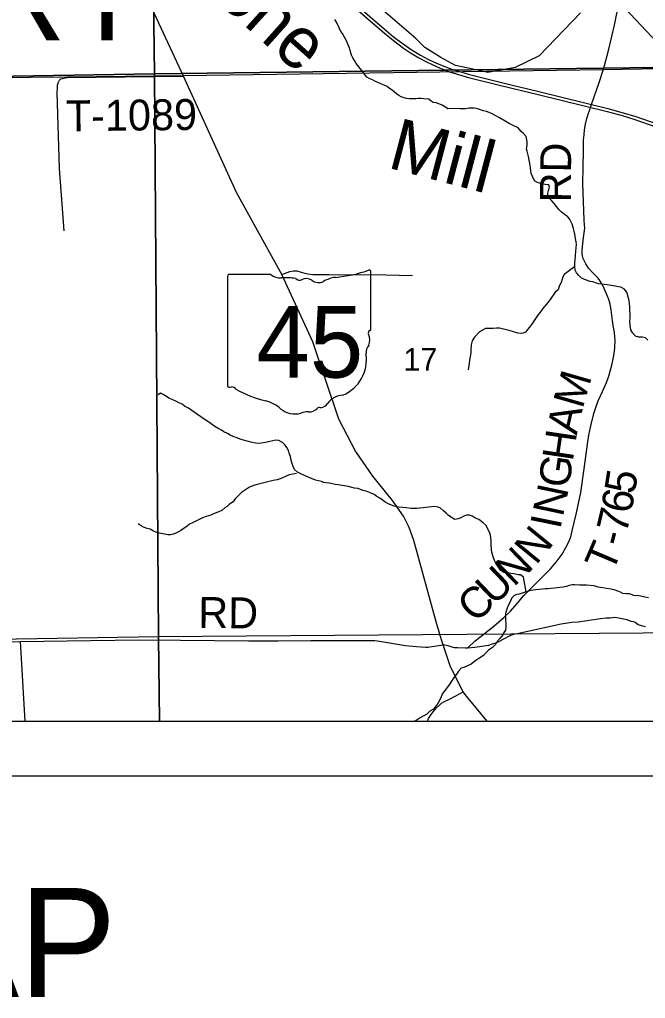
# Model space of a CAD drawing. Extents: x 0 to 34, y 0 to 22.
# Drawn here: x 6.27 to 7.419, y 13.591 to 15.389 of the extents above; entities that cross this region are included whole.
import ezdxf

# ---------------------------------------------------------------- set-up
doc = ezdxf.new("R2010")
doc.units = 0
for name, color, linetype in [('Default', 7, 'Continuous'), ('GM_X_County_Road', 7, 'Continuous'), ('GM_X_County_Road_Text', 7, 'Continuous'), ('GM_X_Minor_River', 7, 'Continuous'), ('GM_X_Minor_River_Text', 7, 'Continuous'), ('GM_X_Rail_Line', 7, 'Continuous'), ('GM_X_Section', 7, 'Continuous'), ('GM_X_Section_Text', 7, 'Continuous'), ('GM_X_State_Location', 7, 'Continuous'), ('GM_X_State_Route', 7, 'Continuous'), ('GM_X_State_Shield', 7, 'Continuous'), ('GM_X_Township', 7, 'Continuous'), ('GM_X_Township_Road', 7, 'Continuous'), ('GM_X_Township_Road_Text', 7, 'Continuous'), ('GM_X_Township_Text', 7, 'Continuous'), ('SH_Cut_Line', 7, 'Continuous'), ('SH_Data', 7, 'Continuous'), ('SH_Text', 7, 'Continuous')]:
    doc.layers.add(name, color=color, linetype=linetype)

msp = doc.modelspace()

# ---------------------------------------------------------------- linework, layer by layer
at = {"layer": 'Default'}
for points in [[(6.527, 14.1), (7.4967, 14.1), (7.496, 14.2624), (6.5252, 14.2552)], [(5.5573, 14.1), (6.527, 14.1), (6.5252, 14.2552), (5.5565, 14.239), (5.5568, 14.2045)]]:
    msp.add_lwpolyline(points, close=True, dxfattribs=at)
at = {"layer": 'GM_X_County_Road'}
msp.add_lwpolyline([(6.1042, 14.2452), (6.2723, 14.2468), (6.4008, 14.2484), (6.4904, 14.2496), (6.5656, 14.249), (6.6904, 14.2481), (6.7452, 14.2479), (6.8053, 14.2482), (6.9126, 14.2485), (6.9224, 14.2483), (6.9269, 14.2479), (6.9311, 14.2473), (6.9603, 14.2421), (6.9789, 14.2394), (6.999, 14.2375), (7.0164, 14.2363), (7.0179, 14.2362), (7.0197, 14.2363), (7.0227, 14.2367), (7.0279, 14.2375), (7.0479, 14.2406)], dxfattribs=at)
at = {"layer": 'GM_X_Minor_River'}
for points in [[(7.2413, 15.0755), (7.243, 15.0812), (7.2422, 15.0857), (7.2353, 15.0864), (7.23, 15.0866), (7.2251, 15.0888), (7.2201, 15.0906), (7.2159, 15.0928), (7.2095, 15.1067), (7.2077, 15.1211), (7.2047, 15.1378), (7.2023, 15.1476), (7.201, 15.1518), (7.202, 15.1583), (7.2023, 15.1643), (7.2018, 15.1685), (7.2006, 15.1746), (7.1955, 15.1802), (7.1913, 15.1839), (7.1855, 15.1902), (7.1767, 15.1946), (7.169, 15.1986), (7.1629, 15.2023), (7.1517, 15.2085), (7.138, 15.2158), (7.1322, 15.2183), (7.1273, 15.2201), (7.1223, 15.2215), (7.1093, 15.2258), (7.1052, 15.2265), (7.0953, 15.2263), (7.0893, 15.2254), (7.0836, 15.2252), (7.079, 15.2255), (7.0684, 15.2257), (7.0563, 15.2254), (7.0521, 15.2284), (7.046, 15.232), (7.0402, 15.2342), (7.0349, 15.236), (7.0299, 15.237), (7.0257, 15.2396), (7.0215, 15.2429), (7.0128, 15.2439), (7.0078, 15.2445), (7.0021, 15.2444), (6.998, 15.2439), (6.9923, 15.2434), (6.9862, 15.2437), (6.9809, 15.2443), (6.9767, 15.2453), (6.971, 15.2471), (6.9668, 15.2497), (6.9622, 15.2526), (6.9541, 15.2593), (6.9495, 15.2626), (6.9452, 15.2663), (6.9399, 15.2689), (6.9334, 15.2714), (6.9223, 15.2761), (6.9181, 15.2783), (6.912, 15.2808), (6.9078, 15.2834), (6.9039, 15.289), (6.8988, 15.2954), (6.893, 15.3025), (6.8883, 15.3088), (6.8852, 15.3141), (6.8824, 15.319), (6.8797, 15.3238), (6.8772, 15.3322), (6.8752, 15.3386), (6.87, 15.3514), (6.8672, 15.3567), (6.8633, 15.3634), (6.8602, 15.3675), (6.8574, 15.3743), (6.8523, 15.3848), (6.8491, 15.3897)], [(7.4235, 14.8004), (7.4192, 14.8048), (7.4132, 14.8058), (7.4071, 14.8057), (7.4014, 14.8078), (7.3963, 14.8134), (7.3928, 14.8194), (7.3911, 14.8278), (7.391, 14.8346), (7.3912, 14.8418), (7.3908, 14.862), (7.3899, 14.8669), (7.3894, 14.8734), (7.3878, 14.879), (7.3865, 14.8851), (7.3838, 14.8896), (7.381, 14.8937), (7.3741, 14.8974), (7.3699, 14.898), (7.3639, 14.8994), (7.3494, 14.9018), (7.3384, 14.9031), (7.3338, 14.9037), (7.3293, 14.9051), (7.3228, 14.9073), (7.3175, 14.9083), (7.3129, 14.9101), (7.3072, 14.9119), (7.3014, 14.9148), (7.2972, 14.9189), (7.2925, 14.9237), (7.2901, 14.929), (7.2896, 14.9354), (7.2899, 14.9423), (7.2901, 14.9476), (7.2911, 14.9552), (7.2917, 14.9636), (7.2923, 14.9697), (7.2926, 14.9758), (7.2921, 14.9811), (7.2912, 14.9872), (7.2895, 14.9948), (7.2883, 15.0004), (7.2874, 15.0057), (7.285, 15.0133), (7.2802, 15.0231), (7.276, 15.0275), (7.271, 15.0312), (7.2652, 15.0353), (7.2606, 15.0401), (7.252, 15.0514), (7.2477, 15.0562), (7.2427, 15.061), (7.2403, 15.0659), (7.2402, 15.0705), (7.2413, 15.0755)], [(7.2896, 14.9354), (7.2702, 14.9209), (7.2677, 14.9167), (7.2662, 14.9125), (7.2649, 14.906), (7.2612, 14.8994), (7.2591, 14.8929), (7.2539, 14.8883), (7.2443, 14.8747), (7.2406, 14.8701), (7.2343, 14.862), (7.2306, 14.8577), (7.2266, 14.8523), (7.2233, 14.848), (7.2192, 14.8426), (7.2163, 14.838), (7.2119, 14.8314), (7.2063, 14.8241), (7.203, 14.8198), (7.1989, 14.8152), (7.1948, 14.8132), (7.1899, 14.8127), (7.1853, 14.8134), (7.1693, 14.8183), (7.164, 14.8194), (7.1564, 14.8211), (7.1514, 14.8221), (7.1461, 14.8224), (7.1397, 14.8219), (7.1257, 14.8216), (7.1205, 14.8188), (7.1148, 14.8156), (7.1056, 14.8059), (7.1012, 14.799), (7.0994, 14.7917), (7.0989, 14.7826), (7.0986, 14.7769), (7.0966, 14.7635), (7.0956, 14.7574), (7.0939, 14.7456)], [(6.6291, 14.6419), (6.6176, 14.6496), (6.6095, 14.6552), (6.603, 14.6592), (6.5868, 14.671), (6.5803, 14.6751), (6.5734, 14.6791), (6.5691, 14.6824), (6.5626, 14.6853), (6.5584, 14.6875), (6.5504, 14.6915), (6.5443, 14.694), (6.5401, 14.697), (6.5343, 14.7003), (6.529, 14.7028), (6.5248, 14.7001)], [(7.2001, 14.3382), (7.1954, 14.3649), (7.19, 14.3689), (7.1859, 14.3692), (7.1809, 14.3703), (7.1653, 14.3726), (7.1596, 14.3736), (7.1535, 14.378), (7.1484, 14.3848), (7.1453, 14.3893), (7.1421, 14.3957), (7.1401, 14.4021), (7.1376, 14.4108), (7.1368, 14.4149), (7.1362, 14.4244), (7.1361, 14.4305), (7.1356, 14.4385), (7.1343, 14.4445), (7.1268, 14.4596), (7.1214, 14.4648), (7.1133, 14.4707), (7.1072, 14.4732), (7.1014, 14.4769), (7.0961, 14.4787), (7.0915, 14.479), (7.087, 14.4777), (7.0807, 14.4738), (7.0758, 14.4718), (7.0697, 14.4705), (7.0632, 14.4742), (7.0571, 14.4786), (7.0536, 14.4827), (7.0489, 14.4868), (7.0432, 14.4916), (7.0386, 14.4934), (7.0321, 14.4944), (7.0162, 14.4929), (7.0113, 14.492), (7.0045, 14.4915), (6.9996, 14.491), (6.9939, 14.4913), (6.9894, 14.4912), (6.9803, 14.4925), (6.9738, 14.4927), (6.9666, 14.4933), (6.9579, 14.4954), (6.9472, 14.4998), (6.943, 14.502), (6.9318, 14.5097), (6.9264, 14.513), (6.9214, 14.5167), (6.9157, 14.5192), (6.9065, 14.5228), (6.9008, 14.5242), (6.8917, 14.5275), (6.8852, 14.5285), (6.8738, 14.5316), (6.8662, 14.5326), (6.8552, 14.5346), (6.8498, 14.5353), (6.8396, 14.5373), (6.8335, 14.538), (6.8286, 14.5386), (6.8244, 14.5404), (6.8137, 14.5429), (6.8091, 14.5447), (6.8042, 14.5465), (6.7866, 14.5548), (6.7808, 14.5577), (6.7754, 14.5629), (6.7726, 14.5682), (6.7702, 14.5758), (6.769, 14.5799), (6.7677, 14.5867), (6.7653, 14.5928), (6.7641, 14.5973), (6.7609, 14.6029), (6.7582, 14.6074), (6.7528, 14.6123), (6.7463, 14.6159), (6.741, 14.6166), (6.7297, 14.614), (6.7221, 14.6124), (6.7142, 14.611), (6.7085, 14.6105), (6.7043, 14.6108), (6.7002, 14.6115), (6.6952, 14.6129), (6.6906, 14.6143), (6.6815, 14.6164), (6.6773, 14.6178), (6.6723, 14.6193), (6.6681, 14.6215), (6.6639, 14.6225), (6.6571, 14.6258), (6.6521, 14.6287), (6.6456, 14.632), (6.641, 14.6349), (6.636, 14.6375), (6.6291, 14.6419)], [(6.7786, 14.555), (6.7722, 14.5541), (6.7654, 14.5528), (6.7586, 14.55), (6.753, 14.5472), (6.7485, 14.5452), (6.7432, 14.5436), (6.7361, 14.5423), (6.7165, 14.5373), (6.7112, 14.5364), (6.7063, 14.5348), (6.6999, 14.5335), (6.6924, 14.53), (6.6853, 14.5252), (6.6778, 14.5201), (6.6663, 14.5089), (6.6623, 14.5031), (6.6559, 14.4991), (6.6518, 14.4945), (6.6473, 14.4921), (6.6414, 14.4874), (6.6361, 14.4846), (6.6279, 14.4818), (6.6215, 14.479), (6.6132, 14.4765), (6.6061, 14.4737), (6.6004, 14.4709), (6.5952, 14.4681), (6.5881, 14.4649), (6.5824, 14.4622), (6.578, 14.4586), (6.5664, 14.4508), (6.5619, 14.4484), (6.557, 14.4456), (6.5525, 14.4436), (6.5472, 14.4428), (6.5427, 14.4427), (6.5275, 14.4454), (6.5225, 14.4468), (6.516, 14.4493), (6.5099, 14.453), (6.5046, 14.4544), (6.4977, 14.4569), (6.4935, 14.4591), (6.4881, 14.4628)], [(7.425, 14.3266), (7.4182, 14.3283), (7.4132, 14.3294), (7.4071, 14.3304), (7.398, 14.3313), (7.39, 14.3342), (7.3847, 14.3344), (7.3779, 14.3351), (7.3733, 14.3372), (7.3637, 14.3408), (7.3561, 14.3426), (7.3477, 14.3443), (7.3409, 14.3453), (7.3325, 14.3466), (7.3253, 14.3487), (7.3109, 14.3503), (7.2984, 14.3504), (7.2893, 14.3506), (7.2847, 14.3505), (7.2791, 14.3496), (7.2742, 14.348), (7.2685, 14.3467), (7.2621, 14.3458), (7.2527, 14.3448), (7.2459, 14.3439), (7.2409, 14.3434), (7.2353, 14.3433), (7.2303, 14.3428), (7.2179, 14.3418), (7.213, 14.3409), (7.2088, 14.3405), (7.2001, 14.338), (7.1874, 14.3339), (7.1832, 14.3331), (7.1783, 14.3314), (7.1739, 14.3268), (7.1717, 14.321), (7.1684, 14.3152), (7.1655, 14.308), (7.1627, 14.2984), (7.1624, 14.2934), (7.1629, 14.2722), (7.1626, 14.2676), (7.1593, 14.2629), (7.1575, 14.2587), (7.1523, 14.2521), (7.1467, 14.2463), (7.1438, 14.2413), (7.1383, 14.2355), (7.1315, 14.2308), (7.1267, 14.2265), (7.1223, 14.2207), (7.1155, 14.2167), (7.1062, 14.2108), (7.0995, 14.205), (7.0927, 14.2022), (7.086, 14.1986), (7.0811, 14.1977), (7.0763, 14.1919), (7.0726, 14.1865), (7.0663, 14.1784), (7.0634, 14.1738), (7.059, 14.1672), (7.0513, 14.1564), (7.0468, 14.151), (7.0443, 14.1448), (7.0392, 14.1348), (7.03, 14.1221), (7.0237, 14.1185), (7.0181, 14.1131), (7.0061, 14.1063), (6.9964, 14.1004), (6.9957, 14.1)]]:
    msp.add_lwpolyline(points, dxfattribs=at)
at = {"layer": 'GM_X_Rail_Line'}
msp.add_lwpolyline([(5.5619, 14.1), (8.9, 14.1), (8.9, 17.3138), (8.2882, 17.3064), (7.4754, 17.3006), (7.4757, 17.0495), (7.4723, 16.4951), (7.4818, 15.827), (7.482, 15.8179), (7.4834, 15.2992), (7.3416, 15.297), (6.5709, 15.2859), (6.3575, 15.2833), (5.5569, 15.2761), (5.5579, 15.2049), (5.5588, 15.1747), (5.5581, 14.9676), (5.5583, 14.9347), (5.5595, 14.6439), (5.5615, 14.2414), (5.5608, 14.205)], close=True, dxfattribs=at)
for points in [[(7.2999, 15.4014), (7.2245, 15.3226), (7.1802, 15.3011), (7.1302, 15.2918), (7.1142, 15.2958), (7.0708, 15.3051), (7.044, 15.3194), (7.0144, 15.338), (6.9981, 15.3543), (6.9592, 15.3878), (6.6469, 15.6574)], [(6.875, 15.4204), (6.936, 15.3678), (6.9535, 15.3534), (6.9645, 15.3449), (6.9755, 15.337), (6.9882, 15.3283), (7.0036, 15.3191), (7.0174, 15.3117), (7.028, 15.3067), (7.041, 15.3008), (7.0599, 15.2935), (7.0948, 15.283), (7.1537, 15.2682), (7.2222, 15.2514), (7.349, 15.2202), (7.3768, 15.2128), (7.3998, 15.2059), (7.4385, 15.1923)], [(6.8787, 15.4247), (6.9396, 15.3721), (6.957, 15.3578), (6.9679, 15.3494), (6.9788, 15.3416), (6.9913, 15.333), (7.0064, 15.324), (7.0199, 15.3167), (7.0304, 15.3118), (7.0432, 15.306), (7.0618, 15.2988), (7.0963, 15.2885), (7.1551, 15.2736), (7.2235, 15.2569), (7.3504, 15.2257), (7.3784, 15.2182), (7.4016, 15.2113), (7.4405, 15.1976)]]:
    msp.add_lwpolyline(points, dxfattribs=at)
at = {"layer": 'GM_X_Section'}
for points in [[(6.5053, 16.2508), (7.4857, 16.2946), (7.4868, 15.3017), (6.5184, 15.2893)], [(5.5468, 16.2132), (6.5053, 16.2508), (6.5184, 15.2893), (5.5538, 15.2739)], [(5.5538, 15.2739), (6.5184, 15.2893), (6.5252, 14.2552), (5.5565, 14.239), (5.5548, 15.2004)], [(6.5184, 15.2893), (7.4868, 15.3017), (7.496, 14.2624), (6.5252, 14.2552)]]:
    msp.add_lwpolyline(points, close=True, dxfattribs=at)
at = {"layer": 'GM_X_State_Route'}
msp.add_line((7.1285, 14.1), (7.0908, 14.1463), dxfattribs=at)
for points in [[(6.6453, 16.2527), (6.7342, 16.135), (6.8206, 16.019), (6.9337, 15.8667), (7.0828, 15.6666), (7.0979, 15.6472), (7.1155, 15.6342), (7.2286, 15.5659), (7.2423, 15.557), (7.2588, 15.5429), (7.2823, 15.5175), (7.371, 15.4215), (7.4407, 15.3469), (7.4836, 15.2986), (7.4861, 15.2958)], [(6.5711, 15.2854), (6.4769, 15.4883), (6.3999, 15.6505), (6.367, 15.7201), (6.3459, 15.7605)], [(6.6913, 15.0305), (6.6687, 15.0715), (6.5711, 15.2854)], [(6.8888, 14.594), (6.8872, 14.5964), (6.8567, 14.6553), (6.8087, 14.7974), (6.7516, 14.9211), (6.6913, 15.0305)], [(7.0479, 14.2406), (7.0452, 14.2497), (7.0352, 14.283), (6.9942, 14.4322), (6.9855, 14.4563), (6.975, 14.477), (6.9548, 14.5058), (6.919, 14.5503), (6.8888, 14.594)], [(7.0908, 14.1463), (7.0845, 14.154), (7.0616, 14.2003), (7.0479, 14.2406)]]:
    msp.add_lwpolyline(points, dxfattribs=at)
at = {"layer": 'GM_X_State_Shield'}
for p, q in [((6.6519, 14.9175), (6.6519, 14.7174)), ((6.7317, 14.9209), (6.6545, 14.9209)), ((6.9155, 14.8212), (6.9155, 14.9259)), ((6.9155, 14.8212), (6.9155, 14.8212))]:
    msp.add_line(p, q, dxfattribs=at)
for centre, radius, start, end in [((6.8216, 15.1937), 0.2796, 275.8445, 288.9065), ((6.9126, 14.9263), 0.00294, 351.8621, 97.738), ((6.6549, 14.9179), 0.00305, 98.1301, 188.1301), ((6.7501, 14.9441), 0.0296, 231.6195, 271.1119), ((6.7599, 14.8086), 0.1064, 80.4867, 94.9883), ((6.7841, 14.9189), 0.00855, 219.7921, 297.1024), ((6.7966, 14.8958), 0.0178, 54.4667, 119.1411), ((6.8195, 14.9275), 0.0214, 233.8562, 294.8282), ((6.8573, 14.8598), 0.0563, 97.3462, 120.7689), ((6.9124, 14.8208), 0.00314, 289.6038, 7.7341), ((6.9149, 14.8135), 0.00454, 107.944, 210.337), ((6.886, 14.8003), 0.0273, 340.033, 23.6496), ((6.9261, 14.7774), 0.0198, 136.8065, 186.9296), ((6.8373, 14.7641), 0.0699, 292.3089, 8.9858), ((6.6549, 14.7169), 0.00308, 171.9584, 258.3066), ((6.6554, 14.7374), 0.0235, 267.339, 280.6039), ((6.6602, 14.7058), 0.00848, 29.7484, 93.2717), ((6.7673, 14.8856), 0.2019, 240.4129, 257.1985), ((6.8668, 14.6612), 0.0383, 94.4031, 142.5768), ((6.7071, 14.6274), 0.0632, 47.1842, 75.836), ((6.8015, 14.6898), 0.0214, 268.777, 315.5493), ((6.8208, 14.6704), 0.00601, 65.7517, 132.6484), ((6.8182, 14.698), 0.0226, 282.8732, 323.2771), ((6.7754, 14.7048), 0.0401, 230.7004, 286.2918), ((6.7986, 14.6356), 0.0329, 85.6951, 111.2099)]:
    msp.add_arc(centre, radius, start, end, dxfattribs=at)
at = {"layer": 'GM_X_Township'}
msp.add_lwpolyline([(7.482, 15.8179), (7.4834, 15.2992), (7.3416, 15.297), (6.5709, 15.2859), (6.3575, 15.2833), (5.5569, 15.2761), (5.5579, 15.2049), (4.0847, 15.1965), (3.5411, 15.1931), (3.5298, 15.9318)], dxfattribs=at)
at = {"layer": 'GM_X_Township_Road'}
msp.add_line((6.2805, 14.1), (6.2723, 14.2468), dxfattribs=at)
for points in [[(7.3442, 15.3047), (7.3513, 15.3325), (7.3623, 15.3789), (7.371, 15.4215)], [(7.3155, 15.2193), (7.3158, 15.2202), (7.3205, 15.2334), (7.3345, 15.2734), (7.3418, 15.2964), (7.3432, 15.3009), (7.3442, 15.3047)], [(6.3521, 15.0011), (6.3438, 15.1158), (6.3396, 15.2552), (6.3399, 15.2639), (6.3403, 15.2689), (6.341, 15.2724), (6.3416, 15.2746), (6.3422, 15.2758), (6.3429, 15.2769), (6.3436, 15.2777), (6.3444, 15.2787), (6.3454, 15.2796), (6.3464, 15.2803)], [(6.3464, 15.2803), (6.3577, 15.2828), (6.5711, 15.2854)], [(7.0936, 14.2353), (7.1069, 14.2477), (7.1408, 14.2748), (7.1591, 14.2906), (7.1718, 14.3026), (7.184, 14.3165), (7.1966, 14.3318), (7.213, 14.3484), (7.2319, 14.3669), (7.2453, 14.3804), (7.2557, 14.3924), (7.2663, 14.407), (7.2734, 14.4194), (7.2785, 14.4298), (7.2822, 14.4391), (7.285, 14.4497), (7.2931, 14.4829), (7.3005, 14.5205), (7.3069, 14.5638), (7.313, 14.609), (7.3154, 14.6257), (7.3171, 14.6341), (7.3196, 14.6451), (7.3249, 14.6653), (7.3292, 14.6783), (7.3328, 14.6886), (7.3405, 14.7062), (7.3478, 14.7226), (7.3521, 14.7344), (7.3546, 14.7432), (7.3575, 14.7542), (7.3596, 14.7631), (7.3613, 14.7721), (7.3625, 14.7805), (7.363, 14.7864), (7.3635, 14.7994), (7.3634, 14.8055), (7.3627, 14.8141), (7.3604, 14.8274), (7.3588, 14.8361), (7.3575, 14.8463), (7.3562, 14.8561), (7.3545, 14.8663), (7.3523, 14.875), (7.3493, 14.8824), (7.3415, 14.8995), (7.3391, 14.9039), (7.3365, 14.9085), (7.3345, 14.9115), (7.3318, 14.9147), (7.3225, 14.9242), (7.3148, 14.9327), (7.3097, 14.9405), (7.3067, 14.9467), (7.3052, 14.9503), (7.304, 14.9549), (7.3035, 14.9594), (7.3034, 14.9644), (7.304, 14.9723), (7.3056, 14.989), (7.3076, 15.002), (7.3079, 15.0067), (7.3076, 15.0118), (7.307, 15.0213), (7.3043, 15.088), (7.3045, 15.0982), (7.3048, 15.1069), (7.305, 15.1179), (7.3052, 15.128), (7.3054, 15.1382), (7.3055, 15.1562), (7.3057, 15.1679), (7.3066, 15.1774), (7.3076, 15.1866), (7.3093, 15.1972), (7.3118, 15.2075), (7.3155, 15.2193)], [(6.7516, 14.9211), (6.7665, 14.9262), (6.7735, 14.9274), (6.7792, 14.9274), (6.7875, 14.9252), (6.7998, 14.9222), (6.8087, 14.9208), (6.8388, 14.9207), (6.9428, 14.9204), (6.9917, 14.9192)], [(7.0479, 14.2406), (7.0511, 14.2404), (7.0541, 14.2399), (7.0567, 14.2394), (7.0587, 14.2389), (7.0659, 14.2363), (7.0683, 14.2358), (7.0704, 14.2356), (7.0746, 14.2354), (7.089, 14.2352), (7.0936, 14.2353), (7.1059, 14.2363), (7.1146, 14.2372), (7.1233, 14.2385), (7.1319, 14.2402), (7.1387, 14.2422), (7.1449, 14.2442), (7.1504, 14.2465), (7.1609, 14.252), (7.1687, 14.2563), (7.1726, 14.2581), (7.176, 14.2595), (7.18, 14.2606), (7.1838, 14.2615), (7.2037, 14.2656), (7.2647, 14.2794), (7.2843, 14.2821), (7.2959, 14.283), (7.3367, 14.2887), (7.3471, 14.29), (7.3545, 14.29), (7.3629, 14.2913), (7.3696, 14.29), (7.3849, 14.287), (7.3925, 14.2843), (7.3972, 14.2833), (7.4006, 14.2823), (7.4063, 14.2779), (7.414, 14.2752), (7.4197, 14.2742)], [(7.0192, 14.1), (7.0213, 14.1052), (7.0257, 14.1125), (7.0295, 14.1176), (7.036, 14.125), (7.0419, 14.1306), (7.0452, 14.1332), (7.049, 14.1357), (7.0595, 14.1408), (7.0715, 14.147), (7.0845, 14.154)]]:
    msp.add_lwpolyline(points, dxfattribs=at)
at = {"layer": 'SH_Cut_Line'}
msp.add_lwpolyline([(2.1, 17.2107), (2.1, 14.1), (8.9, 14.1)], dxfattribs=at)
at = {"layer": 'SH_Data'}
for p, q in [((2.1, 14.1), (8.9, 14.1)), ((2, 14), (9, 14))]:
    msp.add_line(p, q, dxfattribs=at)

# ---------------------------------------------------------------- texts
at = {"layer": 'GM_X_County_Road_Text'}
msp.add_text('RD', height=0.05682, rotation=359.5027, dxfattribs=at).set_placement((6.5983, 14.2716))
at = {"layer": 'GM_X_Minor_River_Text'}
for s, height, rotation, p in [('Stone', 0.09472, 318.1495, (6.5379, 15.5078)), ('Mill', 0.09473, 345.2575, (6.9435, 15.1178))]:
    msp.add_text(s, height=height, rotation=rotation, dxfattribs=at).set_placement(p)
at = {"layer": 'GM_X_Section_Text'}
msp.add_text('17', height=0.04186, rotation=0, dxfattribs=at).set_placement((6.9751, 14.744))
at = {"layer": 'GM_X_State_Location'}
for s in ['s', 'r']:
    msp.add_text(s, height=0.000189, dxfattribs=at).set_placement((6.7807, 14.8041))
msp.add_text('45', height=0.000189, rotation=0, dxfattribs=at).set_placement((6.7331, 14.7903))
at = {"layer": 'GM_X_State_Shield'}
msp.add_text('45', height=0.13184, dxfattribs=at).set_placement((6.7052, 14.7315))
at = {"layer": 'GM_X_Township_Road_Text'}
for s, height, rotation, p in [('T-1089', 0.05682, 0.6653, (6.3557, 15.1839)), ('RD', 0.05682, 89.5037, (7.2824, 15.0532)), ('M', 0.0568, 73.9073, (7.3039, 14.6727)), ('A', 0.0568, 77.2096, (7.2931, 14.6247)), ('H', 0.0568, 81.4773, (7.2859, 14.5764)), ('G', 0.0568, 81.6829, (7.2787, 14.527)), ('5', 0.0568, 80.9958, (7.3995, 14.5158)), ('N', 0.0568, 78.0564, (7.2676, 14.4742)), ('6', 0.0568, 79.8423, (7.3931, 14.4801)), ('7', 0.0568, 76.6601, (7.3843, 14.4427)), ('N', 0.0568, 50.6497, (7.2185, 14.3858)), ('I', 0.0568, 78.492, (7.263, 14.4514)), ('-', 0.0568, 75.7026, (7.3783, 14.4191)), ('T', 0.0568, 66.9331, (7.3586, 14.371)), ('N', 0.0568, 43.9425, (7.1775, 14.3458)), ('U', 0.0568, 43.7867, (7.1413, 14.3111)), ('C', 0.0568, 43.7884, (7.1076, 14.2788))]:
    msp.add_text(s, height=height, rotation=rotation, dxfattribs=at).set_placement(p)
at = {"layer": 'GM_X_Township_Text'}
msp.add_text('PERRY', height=0.17045, rotation=0, dxfattribs=at).set_placement((5.7217, 15.3511))
at = {"layer": 'SH_Text'}
msp.add_text('LOCATION MAP', height=0.2, dxfattribs=at).set_placement((4.4269, 13.5938))

doc.saveas('drawing.dxf')
